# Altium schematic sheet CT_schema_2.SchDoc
size 289 x 230 mm
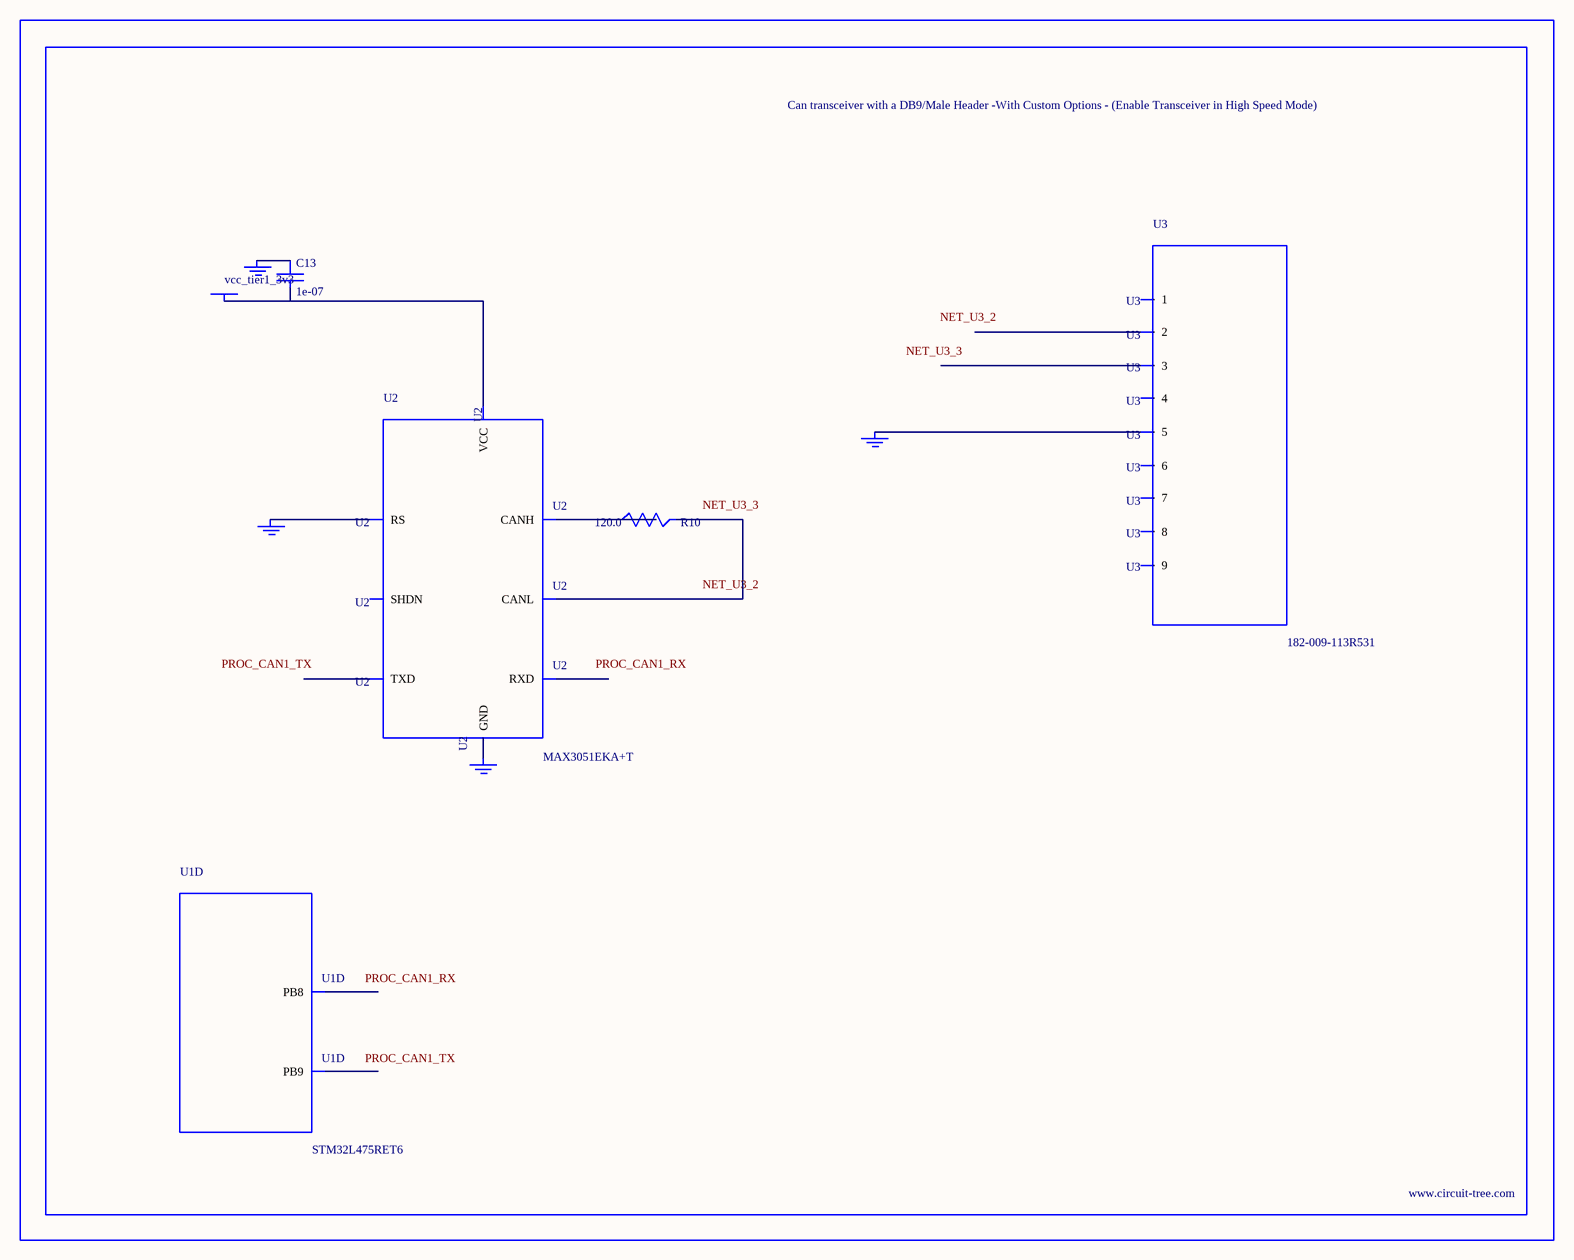
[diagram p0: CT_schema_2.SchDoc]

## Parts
BORDER1  (no value)
C13  1e-07  [C0402]
GND_INSTANCE_1_0  (no value)
GND_INSTANCE_1_1  (no value)
GND_INSTANCE_1_2  (no value)
GND_INSTANCE_1_3  (no value)
POWER_INSTANCE_1_0  vcc_tier1_3v3
R10  120.0  [R0603]
U1  STM32L475RET6  [LQFP64]  (part D of 8)
U2  MAX3051EKA+T  [SOT-23-8]
U3  182-009-113R531  [182-009-MALE]

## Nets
NetC13_1: C13.1 GND_INSTANCE_1_0.0(GND)
NetC13_2: C13.2 POWER_INSTANCE_1_0.0(PWR) U2.3(VCC)
NetGND_INSTANCE_1_1_0: GND_INSTANCE_1_1.0(GND) U2.8(RS)
NetGND_INSTANCE_1_2_0: GND_INSTANCE_1_2.0(GND) U2.2(GND)
NetGND_INSTANCE_1_3_0: GND_INSTANCE_1_3.0(GND) U3.5
NetR10_1: R10.1 U2.7(CANH)
NetR10_2: R10.2 U2.6(CANL)

Not connected (* = marked no-connect by the designer): U1 61(PB8) 62(PB9); U2 1(TXD) 4(RXD) 5(SHDN); U3 1 2 3 4 6 7 8 9

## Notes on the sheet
- Labels drawn without touching a wire or pin: NET_U3_2, NET_U3_3, PROC_CAN1_RX, PROC_CAN1_TX

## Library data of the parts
BORDER1 = BORDER_PAGE1
C13 = C0402C104K3RACTU
GND_INSTANCE_1_0-GND_INSTANCE_1_3 = GND
POWER_INSTANCE_1_0 = PWR
R10 = RC0603JR-07120RL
